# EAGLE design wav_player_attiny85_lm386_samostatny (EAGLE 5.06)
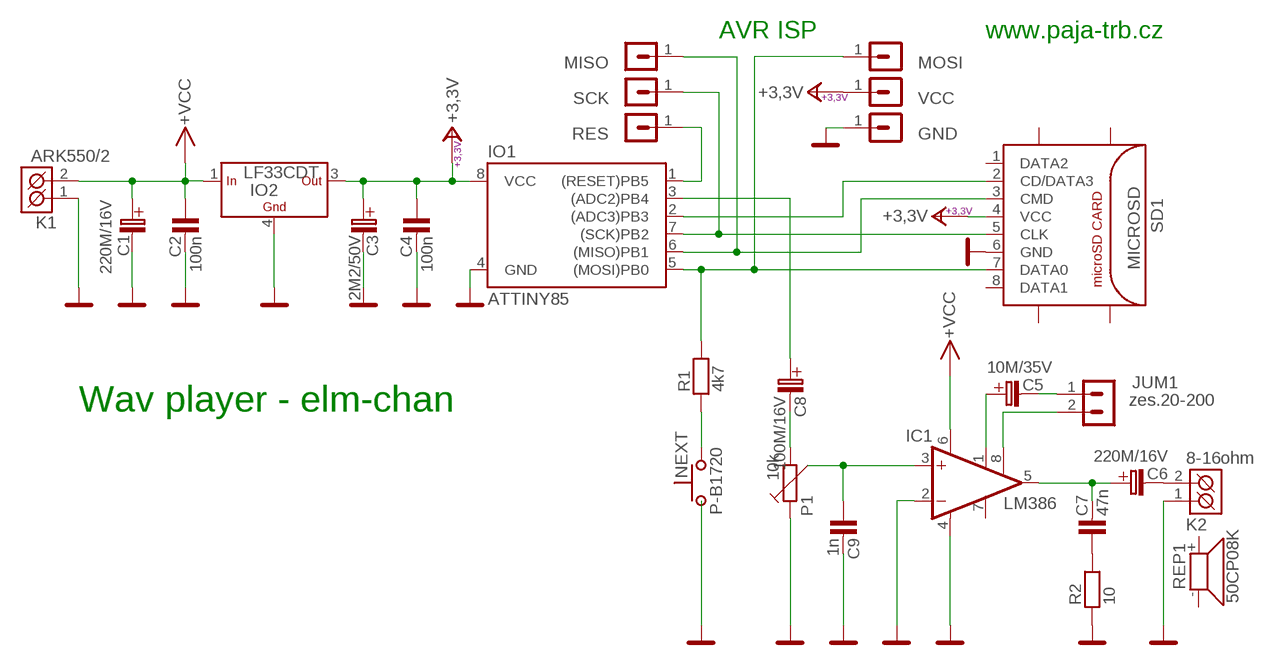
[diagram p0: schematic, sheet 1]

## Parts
C1  220M/16V  [C_EL_3,5]
C2  100n  C-KERAMIK_SMD_1206  [1206]
C3  2M2/50V  [C_EL_2]
C4  100n  C-KERAMIK_7,5  [C-7,5]
C5  10M/35V  [C_EL_2]
C6  220M/16V  [C_EL_3,5]
C7  47n  C-KERAMIK_SMD_1206  [1206]
C8  100M/16V  C-ELEKTROLYT_2,5  [C-EL_2,5]
C9  1n  C-KERAMIK_SMD_1206  [1206]
GND  S1G1_JUMP  [S1G1_JUM]
IC1  LM386  LM386M-1  [SO08]
IO1  ATTINY85  ATTINY13  [SOIC08]
IO2  LF33CDT  LFDPAKDPAKC  [DPAK]
JUM1  zes.20-200  S1G2_JUMP  [S1G2_JUM]
K1  ARK550/2  [ARK550/2]
K2  8-16ohm  ARK550/2  [ARK550/2]
MISO  S1G1_JUMP  [S1G1_JUM]
MOSI  S1G1_JUMP  [S1G1_JUM]
NEXT  P-B1720  [P-B1720]
P1  10k  TRIMRPT6V  [PT6V]
R1  4k7  R_SMD_1206  [1206]
R2  10  R_SMD_1206  [1206]
REP1  50CP08K  REP_50CP08K  [REPRO_50CP08K]
RES  S1G1_JUMP  [S1G1_JUM]
SCK  S1G1_JUMP  [S1G1_JUM]
SD1  MICROSD  [MICRO_SD_CONNECTOR]
VCC  S1G1_JUMP  [S1G1_JUM]

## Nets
+3,3V: C3.C+(C_EL+) C4.1 IO1.8(VCC) IO2.3(OUT) SD1.4(VCC) VCC.1
GND: C1.C-(C_EL-) C2.2 C3.C-(C_EL-) C4.2 C9.2 GND.1 IC1.2(-IN) IC1.4(GND) IO1.4(GND) IO2.4(GND) K1.1(K1) K2.1(K1) NEXT.1 NEXT.3 P1.1 R2.1 SD1.6(GND)
MISO: IO1.6((MISO)PB1) MISO.1 SD1.3(CMD)
MOSI: IO1.5((MOSI)PB0) MOSI.1 R1.2 SD1.7(DATA0)
N$1: C8.C-(C_EL-) P1.2
N$2: IO1.2((ADC3)PB3) SD1.2(CD/DATA3)
N$3: C8.C+(C_EL+) IO1.3((ADC2)PB4)
N$4: IC1.8(GAIN) JUM1.2
N$5: NEXT.2 R1.1
N$6: C5.C-(C_EL-) JUM1.1
N$7: C5.C+(C_EL+) IC1.1(GAIN)
N$8: C9.1 IC1.3(+IN) P1.3
N$10: C6.C+(C_EL+) C7.2 IC1.5(OUT)
N$11: C7.1 R2.2
N$12: C6.C-(C_EL-) K2.2(K2)
RES: IO1.1((RESET)PB5) RES.1
SCK: IO1.7((SCK)PB2) SCK.1 SD1.5(CLK)
VCC: C1.C+(C_EL+) C2.1 IC1.6(VS) IO2.1(IN) K1.2(K2) ; supply symbol labelled +VCC
Unconnected: IC1.7(BYPASS) NEXT.4 REP1.+ REP1.- SD1.1(DATA2) SD1.8(DATA1) SD1.11(CD(1)) SD1.12(CD(2)) SD1.13(CD(3)) SD1.14(CD(4))

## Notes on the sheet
- AVR ISP | www.paja-trb.cz
- Wav player - elm-chan

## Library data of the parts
C1 C6 = #PaJa_C-el_2:220M/16V
C2 C4 C7 C9 = #PaJa_31:C-KERAMIK: Kondenzator - keramicky
C3 = #PaJa_C-el_2:2M2/50V
C5 = #PaJa_C-el_2:10M/35V
C8 = #PaJa_31:C-ELEKTROLYT: Kondenzator - elektrolyticky
GND MISO MOSI RES SCK VCC = #PaJa_konektory:S1G1_JUMP: Radove konektory - koliky - 1x
IC1 = linear:LM386?-*: Low Voltage Audio Power Amplifier Source: http://cache.national.com/ds/LM/LM386.pdf
IO1 = #PaJa_31:ATTINY13: ATMEL ATtiny 13
IO2 = #PaJa_31:LF??C: LF??C - stabilizátory low-drop výstup dle typu 1,25 - 12V
JUM1 = #PaJa_konektory:S1G2_JUMP: Radove konektory - koliky - 2x
K1 K2 = #PaJa_konektory:ARK550/2: Svorkovnice - roztec 3,5mm - dvojita
NEXT = #PaJa_prepinace:P-B1720: &micro;-tlacitko
P1 = #PaJa_31:TRIMR: Trimr
R1 R2 = #PaJa_31:R: Rezistor
REP1 = #PaJa_31:REP_50CP08K: Repro 8ohm 0,3W,
SD1 = #PaJa_konektory:MICROSD: MicroSD socked 112C-TXAR-R01 Attend technology

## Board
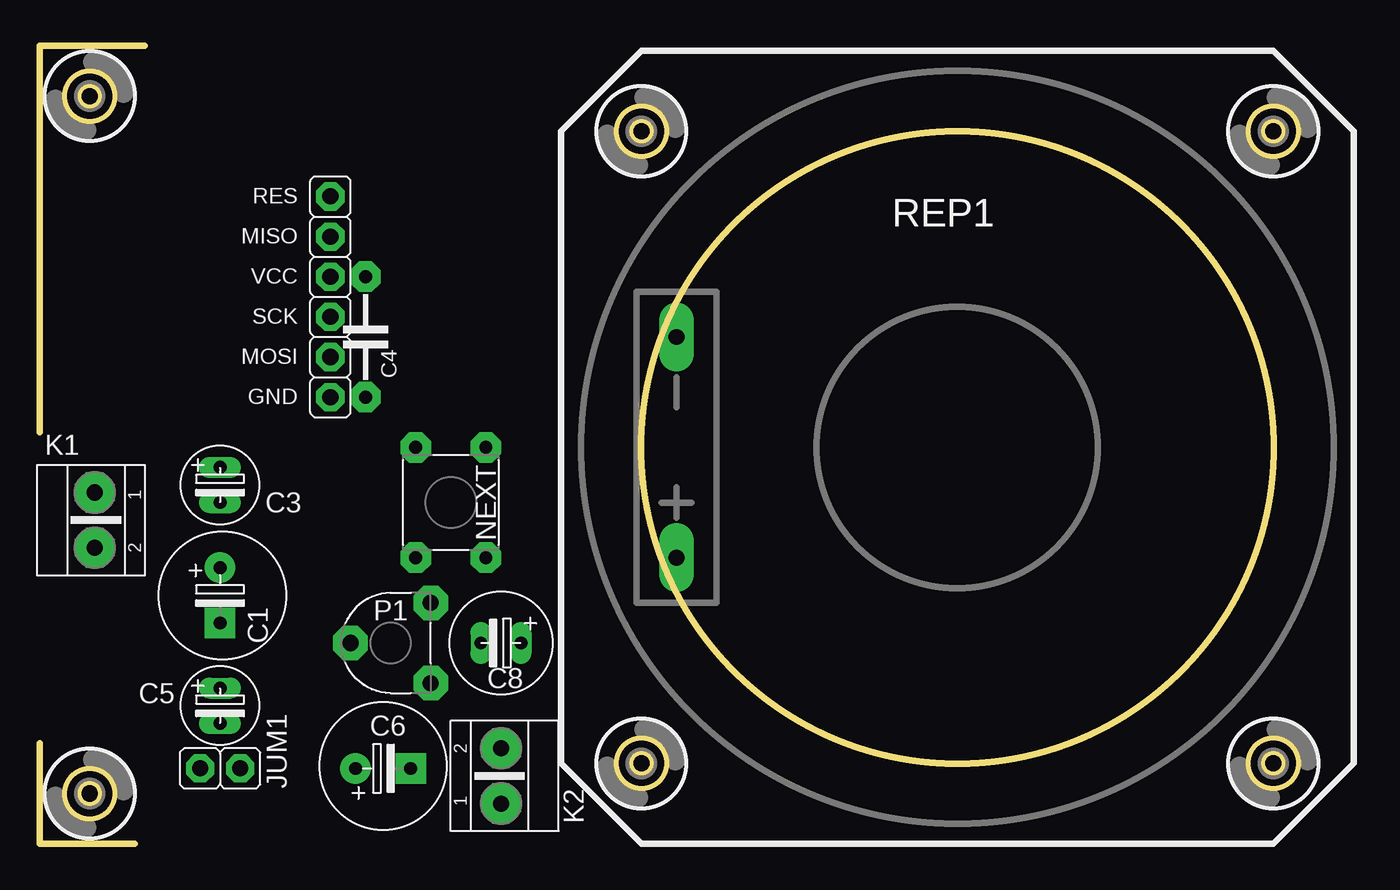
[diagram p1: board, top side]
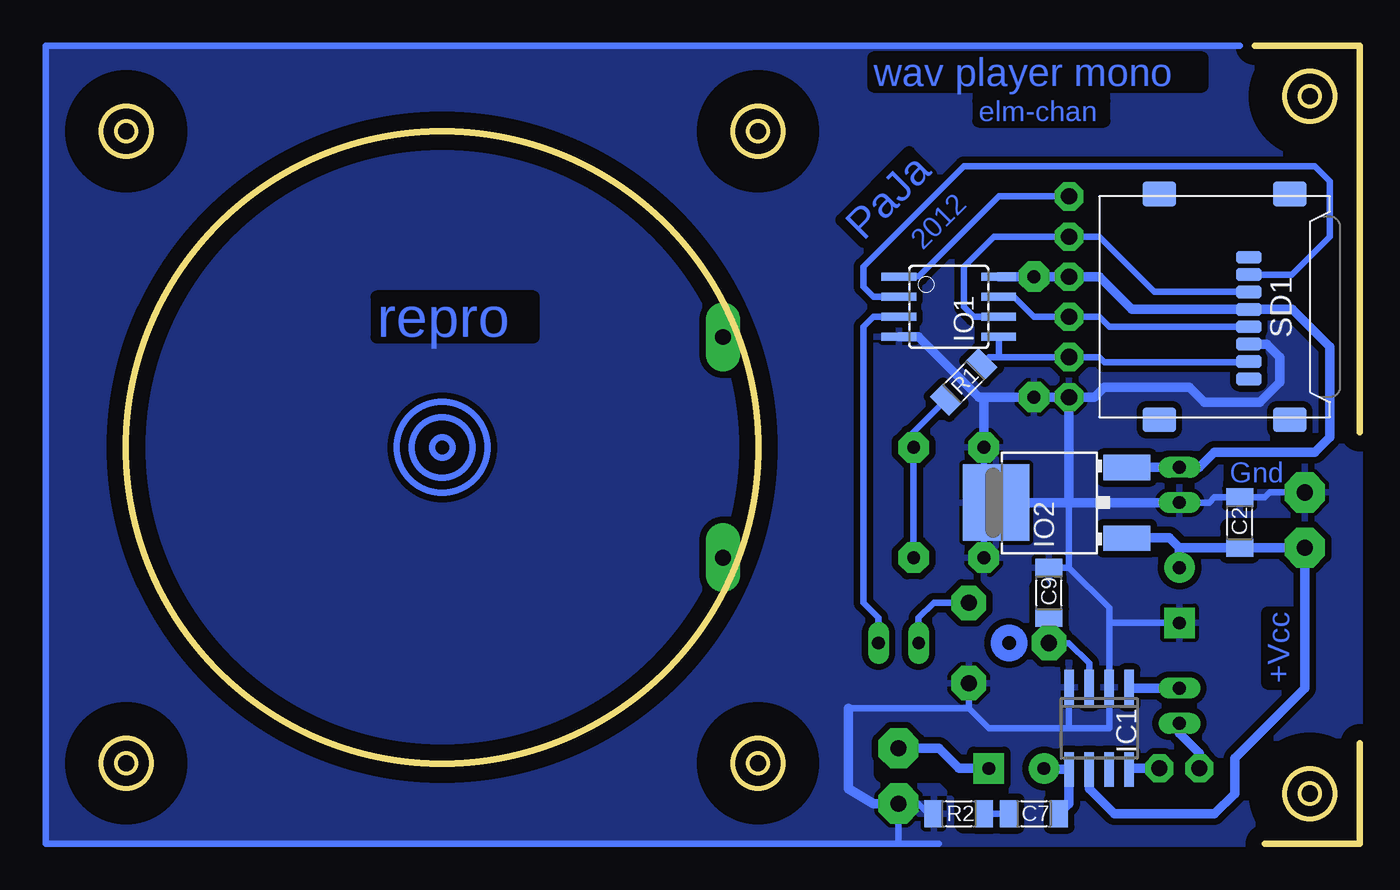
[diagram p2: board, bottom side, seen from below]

Size 79.69 x 50.48 mm. Coordinates in mm from the lower left corner, seen from the top.
Outline: 0,26.04 0,50.48 6.67,50.48
Outline: 6.03,0 0,0 0,6.35
Outline: circle at 3.17,47.31 radius 1.59
Outline: circle at 3.17,3.17 radius 1.59
Outline: circle at 58.1,25.08 radius 20
Copper layers (1*16): Top 0.035mm / dielectric 1.5mm / Bottom 0.035mm
Design rules "default": minimum track width 10mil, minimum drill 24mil, track to track 8mil, track to pad 8mil, pad to pad 8mil, via to via 8mil, smd to smd 8mil, copper to edge 40mil, drill to drill 8mil, minimum pad ring 10mil, minimum via ring 8mil, stop-mask expansion 4mil, vias tented up to drill 0mil, thermal gap 10mil
bRestrict: 10 lines

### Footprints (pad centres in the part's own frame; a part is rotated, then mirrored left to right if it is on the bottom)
C_EL_3,5 = drill 0.813 pad 1.93 round: C+ 0,0 | drill 0.813 pad 1.93 square: C- 3.493,0
1206 = smd 1.143 x 1.702: 1 -1.587,0; 2 1.587,0
C_EL_2 = drill 0.813 pad 1.27 long: C+ 0,0; C- 2.223,0
C-7,5 = drill 0.813 pad 1.93 octagon: 1 -3.81,0; 2 3.81,0
C-EL_2,5 = drill 0.813 pad 1.27 long: C+ -1.27,0; C- 1.27,0
S1G1_JUM = drill 1.016 pad 1.778 octagon: 1 0,0
SO08 = smd 0.6 x 2.2: 1 -1.905,-2.6; 2 -0.635,-2.6; 3 0.635,-2.6; 4 1.905,-2.6; 5 1.905,2.6; 6 0.635,2.6; 7 -0.635,2.6; 8 -1.905,2.6
SOIC08 = smd 2.2 x 0.5: 1 -3.154,1.905; 2 -3.154,0.645; 3 -3.154,-0.625; 4 -3.154,-1.895; 5 3.154,-1.905; 6 3.154,-0.635; 7 3.154,0.635; 8 3.154,1.905
DPAK = smd 1.6 x 2.997: 1 -2.261,-4.928; 3 2.21,-4.928 | smd 4.826 x 4.191: 4 0,3.353
S1G2_JUM = drill 1.016 pad 1.778 octagon: 1 -1.27,0; 2 1.27,0
ARK550/2 = drill 1.016 pad 2.54 octagon: 1 0,0; 2 3.493,0
P-B1720 = drill 0.813 pad 1.93 octagon: 1 -3.493,-2.223; 2 -3.493,2.223; 3 3.493,-2.223; 4 3.493,2.223
PT6V = drill 1.016 pad 2.184 octagon: 1 -2.54,-2.54; 2 2.54,-2.54; 3 0,2.54
REPRO_50CP08K = drill 1 pad 2.184 long: + -17.78,-6.985; - -17.78,6.985 | hole 3.2: 20.003,20.003; -20.003,20.003; -20.003,-20.003; 20.003,-20.003
MICRO_SD_CONNECTOR = smd 0.8 x 1.6: 1 -3.141,1.215; 2 -2.041,1.215; 3 -0.941,1.215; 4 0.159,1.215; 5 1.259,1.215; 6 2.359,1.215; 7 3.459,1.215; 8 4.559,1.215 | smd 1.55 x 2.1: 11 -7.144,3.81; 12 -7.144,-4.445; 13 7.144,-4.445; 14 7.144,3.81
HOLE_3,0 = hole 3.2: 0,0

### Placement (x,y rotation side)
C1  11.43,17.46 270 top
C2  7.62,20.32 90 bottom
C3  11.43,23.81 270 top
C4  20.64,32.07 270 top
C5  11.43,9.84 270 top
C6  20,4.76 0 top
C7  20.64,1.91 0 bottom
C8  29.21,12.7 180 top
C9  19.68,15.88 90 bottom
GND  18.41,28.26 180 top
IC1  16.51,7.3 180 bottom
IO1  26.04,33.97 0 bottom
IO2  19.68,21.59 90 bottom
JUM1  11.43,4.76 0 top
K1  3.49,22.23 270 top
K2  29.21,2.54 90 top
MISO  18.41,38.42 180 top
MOSI  18.41,30.8 180 top
NEXT  26.04,21.59 270 top
P1  22.23,12.7 90 top
R1  25.08,29.21 45 bottom
R2  25.4,1.91 0 bottom
REP1  58.1,25.08 0 top
RES  18.41,40.96 180 top
SCK  18.41,33.34 180 top
SD1  8.26,33.97 270 bottom
U$1  [HOLE_3,0]  3.17,3.17 0 top
U$2  [HOLE_3,0]  78.11,5.08 0 top
U$3  [HOLE_3,0]  3.17,47.31 0 top
U$4  [HOLE_3,0]  38.1,45.09 0 top
U$7  [HOLE_3,0]  78.11,45.09 0 top
U$8  [HOLE_3,0]  38.1,5.08 0 top
VCC  18.41,35.88 180 top

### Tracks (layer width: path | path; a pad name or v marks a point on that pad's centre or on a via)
+3,3V
  Bottom 0.406: C4.1 IO1.8 | 14.74,23.81 IO2.3
  Bottom 0.61: IO1.8 C4.1 VCC.1 16.51,35.88 14.45,33.81 SD1.4 4.29,33.81 1.91,31.43 1.91,25.72 2.86,24.77 9.21,24.77 10.16,23.81 C3.C+ 14.74,23.81
GND
  Bottom 0.406: 29.18,32.07 IO1.4 | IO2.4 23.81,21.59 | 23.81,21.59 NEXT.1 | 23.81,21.59 NEXT.3 | R2.1 27.3,1.91 27.94,2.54 K2.1 29.21,0 | 7.62,50.48 83.19,50.48 83.19,0 29.21,0 | 29.21,0 26.67,0 | 24.77,8.57 32.38,8.57 | 18.41,7.3 IC1.4 | 18.41,7.3 15.88,7.3 IC1.2 15.88,13.65 | 24.77,8.57 P1.1 | 24.77,8.57 23.5,7.3 18.41,7.3 | 15.88,13.65 15.88,14.92 18.41,17.46 | 18.41,17.46 18.41,21.59 | C3.C- 9.53,21.59 9.21,21.91 C2.2 6.03,21.91 5.71,22.23 K1.1 | C1.C- 15.88,13.97 15.88,13.65 | 18.41,17.46 C9.2
  Bottom 0.61: GND.1 C4.2 23.81,28.26 | SD1.6 5.9,31.61 5.08,30.8 5.08,29.21 6.35,27.94 9.84,27.94 10.79,28.89 16.19,28.89 16.83,28.26 GND.1 | 18.41,21.59 IO2.4 | 18.41,21.59 GND.1 | 29.18,32.07 27.94,32.07 24.13,28.26 23.81,28.26 | 18.41,21.59 C3.C- | 32.38,8.57 32.38,3.49 30.8,2.54 K2.1 | NEXT.1 23.81,28.26
  pour Bottom (isolate 0.406): 0,50.48 83.19,50.48 83.19,0 0,0
MISO
  Bottom 0.406: IO1.6 24.45,33.34 25.08,33.97 25.08,36.51 23.18,38.42 MISO.1 16.51,38.42 13.02,34.92 7.05,34.92 SD1.3
MOSI
  Bottom 0.406: SD1.7 7.07,30.48 16.19,30.48 16.51,30.8 MOSI.1 22.86,30.8 | 22.86,32.07 IO1.5 22.86,32.05 22.86,30.8 | 22.86,30.8 23.5,30.8 R1.2
N$1
  Bottom 0.406: P1.2 26.99,15.24 27.94,14.29 C8.C-
N$2
  Bottom 0.406: IO1.2 30.81,34.62 31.43,35.24 31.43,36.51 25.08,42.86 2.86,42.86 1.91,41.91 1.91,38.42 4.31,36.01 SD1.2
N$3
  Bottom 0.406: IO1.3 29.2,33.34 30.8,33.34 31.43,32.7 31.43,15.24 30.48,14.29 C8.C+
N$4
  Bottom 0.406: 14.61,4.76 IC1.8
  Bottom 0.61: JUM1.2 14.61,4.76
N$5  (via drill 0.81 pad 1.93)
  Bottom 0.406: R1.1 28.26,26.04 NEXT.2 v28.26,18.1
N$6
  Bottom 0.61: JUM1.1 10.16,5.71 11.43,6.99 C5.C-
N$7
  Bottom 0.406: 14.61,9.21 14.61,9.84 IC1.1
  Bottom 0.61: C5.C+ 14.61,9.84
N$8
  Bottom 0.406: IC1.3 17.14,11.43 18.41,12.7 P1.3 C9.1
N$10
  Bottom 0.406: 19.94,4.7 C6.C+
  Bottom 0.61: C7.2 18.41,2.54 IC1.5 19.94,4.7
N$11
  Bottom 0.406: C7.1 R2.2
N$12
  Bottom 0.61: C6.C- 25.4,4.76 26.67,6.03 K2.2
N$15
  pour Bottom (isolate 0.406): 36.83,45.72 36.83,4.13 77.47,4.13 77.47,45.72
RES
  Bottom 0.406: IO1.1 29.21,35.9 27.92,35.9 22.86,40.96 RES.1
SCK
  Bottom 0.406: SD1.5 15.88,32.7 16.51,33.34 SCK.1 20.64,33.34 21.91,34.61 IO1.7
VCC
  Bottom 0.406: 14.72,19.37 arc-89 IO2.1 14.72,19.37
  Bottom 0.61: IC1.6 17.14,3.49 15.56,1.91 9.21,1.91 7.94,3.17 7.94,5.4 3.49,9.84 K1.2 C2.1 11.43,18.73 | 11.43,18.73 12.06,19.37 14.72,19.37 | 11.43,18.73 C1.C+
(copper drawn outside any net)
  shapes: Bottom circle x5

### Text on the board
Bottom: wav player mono | elm-chan | 2012 | PaJa | repro | Gnd | +Vcc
